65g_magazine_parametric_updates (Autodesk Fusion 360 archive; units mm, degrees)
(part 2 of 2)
fillet "Fillet14" radius 1
sweep "Sweep2" sketch "follower top profile" TwistAngle 0 TaperAngle 0
extrude "Extrude1" new body sketch "follower top profile" profile of L8 A5 A4 L7 L6 L4 A3 L2 A2 L3 A1 A6 L5 L1 A7 A8 L9 L12 A9 L13 A10 L17 L18 L20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 against normal blind 4 bodies "definesSketchPlane"
sketch "bullet offsetter bump" plane through (0, 0, -0.75) normal (0, 0, 1) x axis (1, 0, 0)
  line L1 (-7.25, 0) -> (7.25, 0)
  line L2 (-7.25, -4) -> (-7.25, 0)
  line L3 (7.25, -4) -> (-7.25, -4)
  line L4 (7.25, 0) -> (7.25, -4)
  line L5 (-10.25, 0) -> (-7.25, 0)
  line L6 (-10.25, -4) -> (-10.25, 0)
  line L7 (-7.25, -4) -> (-10.25, -4)
  line L8 (-7.25, 0) -> (-7.25, -4)
  line L9 (0.1, 0) -> (-10.25, 0)
  line L10 (0.1, 4.5) -> (0.1, 0)
  line L11 (-6.75, 4.5) -> (0.1, 4.5)
  line L12 (-10.25, 0) -> (-10.25, 1)
  line L13 (-10.25, 1) -> (-6.75, 4.5)
  point P7 (-10.25, 0)
  point P10 (-10.25, 0)
  point P13 (-10.25, 0)
  point P12 (-10.25, 4.5)
  point P14 (0.1, 4.5)
  point P15 (0.1, 4.5)
  point P11 (0.1, 0)
  point P16 (-6.75, 4.5)
  point P17 (-10.25, 1)
  coincident P7 P10
  perpendicular L6 L9
  perpendicular L1 L10
  coincident P7 P13
  horizontal L11
  vertical L12
  coincident P12 L11
  coincident P12 L12
  coincident P14 P15
  dimension "d900" distance P10 P11 = 10.35
  dimension "d903" distance P12 P16 = 3.5
  dimension "d904" distance P12 P17 = 3.5 (= "d903")
  dimension "d915" distance P11 P14 = 4.5
extrude "Extrude2" new body sketch "bullet offsetter bump" profile of L1 L5 L9 L10 L11 L12 L13 against normal blind 35.5
fillet "Fillet1" radius 3 2
fillet "Fillet6" radius 4
chamfer "Chamfer2" distance 4 distance 4
fillet "Fillet7" radius 2
fillet "Fillet8" radius 1
extrude "Extrude4" new body sketch "follower top profile" profile of L12 L13 A10 L18 L20 L19 A11 L52 blind -7 from offset -2
sweep "Sweep1" sketch "follower top profile" TwistAngle 0 TaperAngle 0
sweep "Sweep3" sketch "follower top profile" TwistAngle 0 TaperAngle 0
chamfer "Chamfer9" distance 0.7 distance 27
extrude "Extrude8" add sketch "follower top profile" profile of L15 L35 L36 L37 L38 L40 L41 L42 L43 against normal blind 5.5
extrude "Extrude9" add sketch "follower top profile" profile of L9 L35 L36 L37 L38 L40 L41 L42 L43 blind -2 from offset -5.5
fillet "Fillet9" radius 1.5
fillet "Fillet10" radius 1.5
combine "Combine2"
chamfer "Chamfer7" distance 0.5 distance 1
fillet "Fillet11" radius 1
chamfer "Chamfer8" distance 0.5 distance 12
fillet "Fillet12" radius 2
move "Move2"
extrude "Extrude6" add sketch "matchingFloorPlate" profile of L2 L5 L11 L16 L23 L24 L25 L26 A15 A16 A17 A18 along normal blind 7
fillet "Fillet1" radius 0.5
sketch "springRetentionNew" plane through (0, 0, 0) normal (0, 1, 0) x axis (1, 0, 0)
  line L1 (4.25, 36.0809) -> (4.25, 12.5809)
  line L2 (6.25, 36.0809) -> (6.25, 12.5809)
  line L3 (-4.25, 12.5809) -> (-4.25, 36.0809)
  line L4 (-6.25, 12.5809) -> (-6.25, 36.0809)
  line L5 (7.75, 14.9309) -> (6.25, 14.9309)
  line L6 (7.75, 21.9309) -> (7.75, 14.9309)
  line L7 (6.25, 21.9309) -> (7.75, 21.9309)
  line L8 (6.25, 14.9309) -> (6.25, 21.9309)
  line L9 (0, 36.0809) -> (0, 12.5809)
  line L10 (0, 4.25) -> (0, 41.25)
  line L11 (-6.25, 14.9309) -> (-6.25, 21.9309)
  line L12 (-7.75, 14.9309) -> (-6.25, 14.9309)
  line L13 (-6.25, 21.9309) -> (-7.75, 21.9309)
  line L14 (-7.75, 21.9309) -> (-7.75, 14.9309)
  line L15 (2.2447, 6.3309) -> (-1.7458, 6.3309)
  line L16 (8.75, 13.9309) -> (5.25, 13.9309)
  line L17 (8.75, 22.9309) -> (8.75, 13.9309)
  line L18 (5.25, 22.9309) -> (8.75, 22.9309)
  line L19 (5.25, 13.9309) -> (5.25, 22.9309)
  line L20 (-5.25, 22.9309) -> (-8.75, 22.9309)
  line L21 (-5.25, 13.9309) -> (-5.25, 22.9309)
  line L22 (-8.75, 13.9309) -> (-5.25, 13.9309)
  line L23 (-8.75, 22.9309) -> (-8.75, 13.9309)
  arc A1 centre (0, 12.5809) radius 6.25 clockwise from (6.25, 12.5809) to (-6.25, 12.5809)
  arc A2 centre (0, 36.0809) radius 6.25 clockwise from (-6.25, 36.0809) to (6.25, 36.0809)
  arc A3 centre (0, 36.0809) radius 4.25 clockwise from (-4.25, 36.0809) to (4.25, 36.0809)
  arc A4 centre (0, 12.5809) radius 4.25 clockwise from (4.25, 12.5809) to (-4.25, 12.5809)
  point P18 (6.25, 14.9309)
  point P4 (0, 12.5809)
  point P22 (0, 12.5809)
  point P10 (0, 36.0809)
  point P23 (0, 36.0809)
  point P27 (-6.25, 14.9309)
  point P19 (7.75, 14.9309)
  point P28 (-7.75, 14.9309)
  point P20 (7.75, 21.9309)
  point P29 (-7.75, 21.9309)
  point P21 (6.25, 21.9309)
  point P26 (-6.25, 21.9309)
  horizontal L5
  vertical L6
  horizontal L7
  vertical L8
  coincident L2 P18
  coincident P4 P22
  coincident P10 P23
  symmetric P18 L10 P27
  symmetric P19 L10 P28
  symmetric P20 L10 P29
  symmetric P21 L10 P26
  perpendicular L10 L15
  tangent A1 L15
  dimension "d1054" distance P18 P19 = 1.5
  dimension "d1055" distance P18 P21 = 7
  dimension "d1056" distance L5 L15 = 8.6
  dimension "d1065" = 1
  dimension "d1066" = -1
extrude "Extrude7" add sketch "springRetentionNew" profile of A1 A2 A3 L1 L2 A4 L3 L4 L8 L11 L19 L18 L16 L22 L21 L20 against normal blind 4
extrude "Extrude8" add sketch "springRetentionNew" profile of L2 L4 L5 L6 L7 L8 L11 L12 L13 L14 to an object from offset -1.8034
draft "Draft1" Angle1 55 Angle2 0
draft "Draft2" Angle1 55 Angle2 0
chamfer "Chamfer1" distance 0.5
extrude "Extrude9" cut sketch "springRetentionNew" profile of L2 L4 L5 L6 L7 L8 L11 L12 L13 L14 L18 L17 L16 L22 L23 L20 along normal blind 4
fillet "Fillet2" radius 1
sketch "addtlReinforcement" plane through (0, -4, 0) normal (0, -1, 0) x axis (1, 0, 0)
  line L1 (7.75, -15.2462) -> (7.75, -21.6156)
  line L2 (6.43, -13.0458) -> (7.5692, -14.6727)
  line L3 (-7.5692, -14.6727) -> (-6.43, -13.0458)
  line L4 (-7.75, -21.6156) -> (-7.75, -15.2462)
  line L5 (-6.4308, -23.8149) -> (-7.5692, -22.1892)
  line L6 (-6.25, -36.0809) -> (-6.25, -24.3885)
  line L7 (6.25, -24.3885) -> (6.25, -36.0809)
  line L8 (7.5692, -22.1892) -> (6.4308, -23.8149)
  line L9 (-6.2963, -24.0877) -> (6.2963, -24.0877)
  line L10 (6.2977, -12.7801) -> (-6.2977, -12.7801)
  line L11 (7.75, -17.0877) -> (-7.75, -17.0877)
  line L12 (-7.75, -20.0877) -> (7.75, -20.0877)
  arc A1 centre (6.75, -21.6156) radius 1 clockwise from (7.75, -21.6156) to (7.5692, -22.1892)
  arc A2 centre (6.75, -15.2462) radius 1 clockwise from (7.5692, -14.6727) to (7.75, -15.2462)
  arc A3 centre (7.2492, -12.4723) radius 1 clockwise from (6.43, -13.0458) to (6.2493, -12.4872)
  arc A4 centre (0, -12.5809) radius 6.25 clockwise from (-6.2493, -12.4872) to (6.2493, -12.4872)
  arc A5 centre (-7.2492, -12.4723) radius 1 clockwise from (-6.2493, -12.4872) to (-6.43, -13.0458)
  arc A6 centre (-6.75, -15.2462) radius 1 clockwise from (-7.75, -15.2462) to (-7.5692, -14.6727)
  arc A7 centre (-6.75, -21.6156) radius 1 clockwise from (-7.5692, -22.1892) to (-7.75, -21.6156)
  arc A8 centre (-7.25, -24.3885) radius 1 clockwise from (-6.4308, -23.8149) to (-6.25, -24.3885)
  arc A9 centre (0, -36.0809) radius 6.25 clockwise from (6.25, -36.0809) to (-6.25, -36.0809)
  arc A10 centre (7.25, -24.3885) radius 1 clockwise from (6.25, -24.3885) to (6.4308, -23.8149)
  point P30 (6.2963, -24.0877)
  point P31 (-6.2963, -24.0877)
  point P32 (-6.2977, -12.7801)
  point P33 (6.2977, -12.7801)
  point P34 (-7.75, -17.0877)
  point P35 (7.75, -17.0877)
  point P36 (7.75, -20.0877)
  point P37 (-7.75, -20.0877)
  midpoint A10 P30
  midpoint A8 P31
  midpoint A5 P32
  midpoint A3 P33
  coincident L4 P34
  coincident L1 P35
  perpendicular L1 L11
  coincident L1 P36
  coincident L4 P37
  perpendicular L4 L12
  dimension "d1071" distance L11 L12 = 3
  dimension "d1072" distance L9 L12 = 4
extrude "Extrude10" add sketch "addtlReinforcement" profile of L1 L4 L11 L12 along normal blind 1 taper -30
fillet "Fillet3" radius 2 1
fillet "Fillet4" radius 0.25
fillet "Fillet5" radius 0.5
sketch "Sketch1" plane through (0, 0, 0) normal (1, 0, 0) x axis (0, 1, 0)
  line L1 (5.675, 0) -> (0, 0)
  line L2 (5.9411, 0.38) -> (5.675, 0)
  line L3 (5.9411, 1.45) -> (5.9411, 0.38)
  line L4 (4.775, 1.45) -> (5.9411, 1.45)
  line L5 (4.775, 2.64) -> (4.775, 1.45)
  line L6 (5.626, 3.1808) -> (4.775, 2.64)
  line L7 (5.0285, 30.441) -> (5.626, 3.1808)
  line L8 (4.305, 32.735) -> (5.0285, 30.441)
  line L9 (4.28, 38.81) -> (4.305, 32.735)
  line L10 (0, 38.7924) -> (4.28, 38.81)
  line L11 (0, 0) -> (0, 38.7924)
  line L12 (3.95, 38.7924) -> (0, 38.7924)
  line L13 (0, 55.88) -> (0, 38.7924)
  line L14 (0, 0) -> (0, 55.88)
  curve K1 (0, 55.88) -> (3.95, 38.7924)
  curve K2 (-0.929, 55.88) -> (0.929, 55.88)
  curve K3 (3.95, 40.5596) -> (3.95, 37.0251)
  point P1 (0, 0)
  point P2 (0, 0)
  point P15 (0, 0)
  point P14 (0, 55.88)
  point P13 (3.95, 38.7924)
  point P3 (5.675, 0)
  point P6 (4.775, 1.45)
  point P7 (4.775, 2.64)
  point P4 (5.9411, 0.38)
  point P5 (5.9411, 1.45)
  point P8 (5.626, 3.1808)
  point P9 (5.0285, 30.441)
  point P10 (4.305, 32.735)
  point P11 (4.28, 38.81)
  point P12 (0, 38.7924)
  coincident P1 P2
  horizontal L1
  perpendicular L1 L3
  perpendicular L3 L4
  perpendicular L4 L5
  perpendicular L9 L10
  vertical L11
  perpendicular L11 L12
  perpendicular L12 L13
  coincident P1 P15
  midpoint P14 K2
  horizontal K2
  midpoint P13 K3
  vertical K3
  dimension "d1114" distance P2 P3 = 5.675 (= "( 11.35 / 2 ) * 1 mm")
  dimension "d1115" distance L5 L11 = 4.775 (= "( 9.55 / 2 ) * 1 mm")
  dimension "d1116" distance P6 P7 = 1.19
  dimension "d1117" distance L1 L4 = 1.45
  dimension "d1120" angle L1 L2 = 125 (= "90 deg + 35 deg")
  dimension "d1121" distance P4 P5 = 1.07
  dimension "d1122" distance P8 L11 = 5.626 (= "( 11.252 / 2 ) * 1 mm")
  dimension "d1123" distance P9 L11 = 5.0285 (= "( 10.057 / 2 ) * 1 mm")
  dimension "d1124" distance L1 P9 = 30.441
  dimension "d1125" distance L1 P10 = 32.735
  dimension "d1126" distance P10 L11 = 4.305 (= "( 8.61 / 2 ) * 1 mm")
  dimension "d1127" distance P11 L11 = 4.28 (= "( 8.56 / 2 ) * 1 mm")
  dimension "d1129" distance L1 P11 = 38.81
  dimension "d1130" distance P12 P13 = 3.95
  dimension "d1131" distance P1 P14 = 55.88
  dimension "d1136" angle L7 L11 = 1.256
revolve "Revolve1" sketch "Sketch1" AlongAngle 360
sketch "Sketch2" plane through (0, 0, 0) normal (0, 0, -1) x axis (-1, 0, 0)
  line L1 (84.8237, -5.675) -> (-1.9926, -5.675)
  line L2 (-1.9926, 16.325) -> (-1.9926, -5.675)
  line L3 (84.8237, 16.325) -> (-1.9926, 16.325)
  line L4 (84.8237, 16.325) -> (84.8237, -5.675)
  circle C1 centre (0, 0) radius 5.675
  circle C2 centre (0, 0) radius 2.1971
  point P1 (0, 0)
  point P3 (0, 0)
  point P4 (-1.9926, -5.675)
  point P6 (-1.9926, 16.325)
  coincident P1 P3
  horizontal L1
  tangent C1 L1
  perpendicular L1 L2
  perpendicular L2 L3
  dimension "d1133" diameter C2 = 4.3942
  dimension "d1138" distance P4 P6 = 22
extrude "Extrude1" cut sketch "Sketch2" profile of C2 against normal blind 3.1242
copy_paste_bodies "CopyPasteBodies2"
move "Move2"
copy_paste_bodies "CopyPasteBodies3"
move "Move3"
move "Move4"
copy_paste_bodies "CopyPasteBodies4"
move "Move5"
copy_paste_bodies "CopyPasteBodies5"
move "Move6"
copy_paste_bodies "CopyPasteBodies6"
move "Move7"
copy_paste_bodies "CopyPasteBodies7"
move "Move8"
copy_paste_bodies "CopyPasteBodies8"
move "Move9"
copy_paste_bodies "CopyPasteBodies9"
move "Move10"
copy_paste_bodies "CopyPasteBodies10"
move "Move11"
move "Move12"
move "Move13"
move "Move14"
move "Move15"
move "Move16"
move "Move17"
move "Move18"
move "Move19"
extrude "Extrude1" new body sketch "Sketch2" against normal blind 60
draft "Draft1" Angle1 -1.25 Angle2 0
shell "Shell1" outerThickness 2
sketch "Sketch1" plane through (0, 18.3168, 0.3997) normal (0, 0.9998, 0.0218) x axis (1, 0, 0)
  line L1 (-86.8237, 2.4002) -> (3.9926, 2.4002)
  line L2 (-86.8237, -61.615) -> (-86.8237, 2.4002)
  line L3 (3.9926, -61.615) -> (-86.8237, -61.615)
  line L4 (3.9926, 2.4002) -> (3.9926, -61.615)
  line L5 (-5.0074, -52.615) -> (-77.8237, -52.615)
  line L6 (-5.0074, -6.5998) -> (-5.0074, -52.615)
  line L7 (-77.8237, -6.5998) -> (-5.0074, -6.5998)
  line L8 (-77.8237, -52.615) -> (-77.8237, -6.5998)
  curve K1 (-46.7288, -36.635) -> (-43.8154, -53.9119)
  curve K2 (-43.8154, -53.9119) -> (-54.0221, -39.671)
  line L9 (-48.7358, -30.8899) -> (-46.4242, -36.508)
  line L10 (-56.6846, -34.1988) -> (-54.3268, -39.7977)
  line L11 (-48.9495, -28.494) -> (-48.7358, -30.8899)
  line L12 (-58.2341, -32.359) -> (-56.6846, -34.1988)
  line L13 (-58.8742, -3.0977) -> (-48.9495, -28.494)
  line L14 (-69.2621, -7.4219) -> (-58.2341, -32.359)
  line L15 (-69.2621, -7.4219) -> (-68.6843, -6.5956)
  line L16 (-58.8742, -3.0977) -> (-59.8677, -2.9255)
  line L17 (-60.3249, -1.8271) -> (-59.8677, -2.9255)
  line L18 (-69.1415, -5.4973) -> (-68.6843, -6.5956)
  line L19 (-59.6597, -0.3909) -> (-59.2485, -1.3787)
  line L20 (-70.6293, -4.9573) -> (-70.2181, -5.9451)
  line L21 (-70.6293, -4.9573) -> (-70.5297, -4.5042)
  line L22 (-59.6597, -0.3909) -> (-60.0513, -0.1423)
  closed curve K3 centre (-53.5918, -30.4265)
  closed curve K4 centre (-64.0681, -5.2598)
  closed curve K5 centre (-50.3755, -38.1528)
  closed curve K6 centre (-64.7333, -3.6619)
  closed curve K7 centre (-64.7333, -3.6619)
  closed curve K8 centre (-65.2905, -2.3233)
  dimension "d1148" = -9
  dimension "d1153" angle L8 L14 = 23.856
extrude "Extrude2" cut sketch "Sketch1" profile of L7 L8 L6 L5 against normal blind 65
extrude "Extrude3" cut of existing geometry blind -10
sketch "Sketch3" plane through (0, 0, -2) normal (0, 0, -1) x axis (-1, 0, 0)
  line L1 (86.8237, -7.7191) -> (-3.9926, -7.7191)
  line L2 (86.8237, 18.3691) -> (86.8237, -7.7191)
  line L3 (-3.9926, 18.3691) -> (86.8237, 18.3691)
  line L4 (-3.9926, -7.7191) -> (-3.9926, 18.3691)
  line L5 (84.8237, 16.325) -> (84.8237, -5.675)
  line L6 (84.8237, -5.675) -> (-1.9926, -5.675)
  line L7 (84.8237, 16.325) -> (-1.9926, 16.325)
  line L8 (79.3394, 16.325) -> (79.3394, -5.675)
  line L9 (68.6888, -5.675) -> (79.3394, -5.675)
  line L10 (74.8883, 8.8792) -> (68.6888, 1.5284)
  line L11 (74.8883, 16.325) -> (74.8883, 8.8792)
  line L12 (68.6888, 1.5284) -> (68.6888, -5.675)
  point P10 (79.3394, -5.675)
  point P11 (79.3394, 16.325)
  point P12 (68.6888, -5.675)
  point P15 (74.8883, 16.325)
  coincident L6 P10
  coincident L7 P11
  perpendicular L7 L8
  coincident L6 P12
  coincident L7 P15
  perpendicular L7 L11
  perpendicular L6 L12
extrude "Extrude3" new body sketch "Sketch3" profile of L6 L7 L8 L9 L10 L11 L12 blind -53 from offset -4
move "Move20"
remove_body "RemoveBody2"
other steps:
base_feature "Base Feature2"
base_feature "Base Feature3"
base_feature "Base Feature4"
base_feature "Base Feature5"
base_feature "Base Feature6"
base_feature "Base Feature7"
base_feature "Base Feature8"
base_feature "Base Feature9"
base_feature "Base Feature10"
derived_base_feature "Derived Base Feature1" bodies "floor plate"
extrude "Extrude4" cut sketch "cut draft angle between feed lips" profile of L1 L2 L3 L4 L5 against normal blind 13.5
extrude "Extrude11" cut sketch "Rear locking lug profile" profile of L3 A1 L6 L7 L8 distance 5.8
create_component "CreateComponent2"
create_component "CreateComponent3"
create_component "CreateComponent4"
create_component "CreateComponent5"
create_component "CreateComponent6"
named bodies: "follower", "mag body", "feed geometry", "random cube", "placeholder to establish center", "SUPPORT V1", "feed geometry (1)", "main body", "draft tool", "feed lip", "feed lip (1)", "floor plate", "floorPlate", "true rear lock lug", "MagpulFollower_223556", "MagpulFollower_223556 (1)", "MagpulFollower_223556 (2)", "MagpulFollower_223556 (3)", "MagpulFollower_223556 (4)", "definesSketchPlane", "Follower", "updated lock lug", "template lock lug from m76", "updated locking lug"

design "65_g_floorplate"
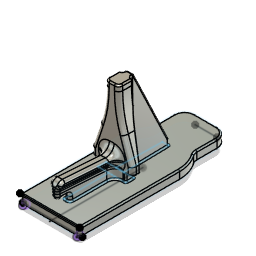
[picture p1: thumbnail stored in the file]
sketch "top profile" plane through (0, 0, 0) normal (0, 1, 0) x axis (1, 0, 0)
  line L1 (20.7, 0) -> (0, 0)
  line L2 (20.7, 38.9995) -> (20.7, 0)
  line L3 (18.085, 52.7) -> (18.085, 38.9995)
  line L4 (5.315, 55.4) -> (15.385, 55.4)
  line L5 (2.615, 39.6) -> (2.615, 52.7)
  line L6 (0, 39.6) -> (2.615, 39.6)
  line L7 (0, 0) -> (0, 39.6)
  line L8 (2.615, 39.6) -> (0, 39.6)
  line L9 (20.7, 38.9995) -> (18.085, 38.9995)
  curve K1 (20.7, 38.9995) -> (18.085, 44.77)
  curve K2 (19.0439, 42.5779) -> (18.3507, 43.501)
  line L10 (10.35, 55.4) -> (10.35, 0)
  curve K3 (0, 38.9995) -> (2.615, 44.77)
  curve K4 (18.1695, 43.9977) -> (18.0005, 45.5423)
  curve K5 (20.6925, 38.3395) -> (20.7075, 39.6594)
  curve K6 (2.5305, 43.9977) -> (2.6995, 45.5423)
  curve K7 (1.6561, 42.5779) -> (2.3493, 43.501)
  curve K8 (0.0075, 38.3395) -> (-0.0075, 39.6594)
  line L11 (0, 38.9995) -> (2.615, 38.9995)
  line L12 (2.615, 55.4) -> (2.615, 38.9995)
  line L13 (10.35, 0) -> (0, 0)
  line L14 (10.35, 36.4) -> (10.35, 0)
  line L15 (0, 36.4) -> (10.35, 36.4)
  line L16 (0, 0) -> (0, 36.4)
  line L17 (5.175, 28.09) -> (5.175, 36.4)
  line L18 (0, 29.925) -> (0, 36.4)
  line L19 (4.421, 36.4) -> (0, 36.4)
  line L20 (5.563, 36.4) -> (4.421, 36.4)
  line L21 (0, 992.6) -> (0, 0)
  line L22 (66.3724, 992.6) -> (0, 992.6)
  arc A1 centre (5.315, 52.7) radius 2.7 clockwise from (2.615, 52.7) to (5.315, 55.4)
  arc A2 centre (15.385, 52.7) radius 2.7 clockwise from (15.385, 55.4) to (18.085, 52.7)
  point P1 (0, 0)
  point P2 (0, 0)
  point P10 (18.085, 44.77)
  point P11 (18.6973, 43.0394)
  point P4 (20.7, 38.9995)
  point P20 (0, 38.9995)
  point P6 (18.085, 38.9995)
  point P31 (2.615, 38.9995)
  point P7 (18.085, 55.4)
  point P32 (2.615, 55.4)
  point P17 (2.615, 44.77)
  point P18 (2.0027, 43.0394)
  point P12 (20.041, 41.5358)
  point P19 (0.659, 41.5358)
  point P13 (18.3507, 43.501)
  point P27 (2.3493, 43.501)
  point P14 (19.0439, 42.5779)
  point P28 (1.6561, 42.5779)
  point P21 (18.0005, 45.5423)
  point P25 (2.6995, 45.5423)
  point P22 (18.1695, 43.9977)
  point P26 (2.5305, 43.9977)
  point P23 (20.7075, 39.6594)
  point P29 (-0.0075, 39.6594)
  point P24 (20.6925, 38.3395)
  point P30 (0.0075, 38.3395)
  point P16 (10.35, 55.4)
  point P8 (2.615, 55.4)
  point P15 (10.35, 0)
  point P3 (20.7, 0)
  point P43 (0, 0)
  point P46 (0, 36.4)
  point P47 (5.175, 36.4)
  point P41 (0, 0)
  point P42 (0, 0)
  point P40 (20.7, 0)
  point P52 (0, 0)
  point P44 (10.35, 0)
  point P45 (10.35, 36.4)
  point P48 (5.175, 28.09)
  point P49 (0, 29.925)
  point P50 (4.421, 36.4)
  point P51 (5.563, 36.4)
  point P53 (0, 992.6)
  coincident P1 P2
  horizontal L1
  perpendicular L1 L2
  perpendicular L3 L4
  perpendicular L1 L7
  perpendicular L5 L8
  perpendicular L2 L9
  coincident L3 P10
  midpoint P11 K2
  midpoint P10 K4
  midpoint P4 K5
  symmetric P4 L10 P20
  symmetric P6 L10 P31
  symmetric P7 L10 P32
  symmetric P10 L10 P17
  symmetric P11 L10 P18
  symmetric P12 L10 P19
  symmetric P13 L10 P27
  symmetric P14 L10 P28
  symmetric L10 P21 P25
  symmetric L10 P22 P26
  symmetric L10 P23 P29
  symmetric L10 P24 P30
  coincident L4 P16
  coincident P8 L4
  coincident P8 L5
  tangent L4 A1
  tangent L5 A1
  coincident P7 L3
  coincident P7 L4
  tangent L3 A2
  tangent L4 A2
  coincident L1 P15
  coincident P3 L1
  coincident P3 L2
  coincident P2 L1
  coincident P1 P43
  perpendicular L10 L13
  perpendicular L1 L14
  coincident L7 P46
  perpendicular L7 L15
  midpoint L15 P47
  perpendicular L15 L17
  perpendicular L15 L18
  perpendicular L7 L19
  perpendicular L17 L20
  coincident P1 P41
  parallel L1 L13
  coincident P2 P42
  coincident P3 P40
  coincident P2 P52
  perpendicular L13 L21
  perpendicular L21 L22
  dimension "d1" distance P2 P3 = 20.7
  dimension "d5" distance P7 P8 = 15.47
  dimension "d7" radius A1 = 2.7
  dimension "d8" radius A2 = 2.7
  dimension "d11" distance P43 P44 = 10.35
  dimension "d12" distance P44 P45 = 36.4
  dimension "d13" distance P47 P48 = 8.31
  dimension "d14" distance P46 P49 = 6.475
  dimension "d15" distance P46 P50 = 4.421
  dimension "d16" distance P50 P51 = 1.142
  dimension "d55" distance P52 P53 = 992.6
  dimension "d263" diameter = 11.2
  dimension "d264" diameter = 11.2
  dimension "d265" diameter = 11.2
  dimension "d266" distance = 5.6
  dimension "d267" distance = 9.5
  dimension "d268" distance = 4.5
  dimension "d269" distance = 5.6
  dimension "d270" distance = 0.5495
  dimension "d271" diameter = 11.2
  dimension "d272" diameter = 11.2
  dimension "d273" diameter = 11.2
  dimension "d274" diameter = 11.2
  dimension "d275" diameter = 11.2
  dimension "d276" distance = 22
  dimension "d277" diameter = 11.2
  dimension "d278" distance = 22
  dimension "d279" diameter = 11.2
  dimension "d280" diameter = 11.2
  dimension "d281" diameter = 11.2
  dimension "d282" distance = 9.5
  dimension "d283" distance = 4.5
  dimension "d284" diameter = 11.2
  dimension "d285" distance = 4.5
  dimension "d286" distance = 9.5
  dimension "d287" distance = 54.4
  dimension "d296" distance = 47
  dimension "d298" distance = 7
  dimension "d299" distance = 5
  dimension "d300" distance = 20
  dimension "d301" distance = 32
  dimension "d302" distance = 36
extrude "Extrude1" new body sketch "top profile" profile of L1 L7 L10 L13 L14 L15 L16 L18 L20 along normal blind 4.5
fillet "Fillet1" radius 3
sketch "uppermost feature" plane through (0, 4.5, 0) normal (0, 1, 0) x axis (-1, 0, 0)
  line L1 (0, -36.4) -> (-10.35, -36.4)
  line L2 (0, 0) -> (0, -36.4)
  line L3 (-10.35, 0) -> (0, 0)
  line L4 (-10.35, -36.4) -> (-10.35, 0)
split "Split1"
combine "Combine1"
chamfer "Chamfer2" distance 4 Rotate Angle 30
chamfer "Chamfer4" distance 3 Rotate Angle 60
draft "Draft2" Angle1 40 Angle2 0
chamfer "Chamfer5" distance 3 Rotate Angle 50
fillet "Fillet4" radius 3
fillet "Fillet5" radius 1.25
fillet "Fillet6" radius 9.5
fillet "Fillet7" radius 2
fillet "Fillet8" radius 1.5
fillet "Fillet9" radius 10.5
fillet "Fillet10" radius 1.5
revolve "Revolve1" sketch "top profile" AlongAngle -0.183
offset_faces "OffsetFaces1" distance 4
offset_faces "OffsetFaces2" distance 4
fillet "Fillet11" radius 11
fillet "Fillet12" radius 4.5
fillet "Fillet13" radius 2
fillet "Fillet14" radius 2
fillet "Fillet15" radius 0.75
sketch "bottom spring support" plane through (0, -3.1703, -0.0101) normal (0, -1, -0.0032) x axis (-1, 0, 0)
  line L1 (0, 35.8746) -> (0, 1.9949)
  line L2 (-2.615, 52.6949) -> (-2.615, 44.4901)
  line L3 (-15.385, 55.3949) -> (-5.315, 55.3949)
  line L4 (-18.085, 44.4901) -> (-18.085, 52.6949)
  line L5 (-20.7, 1.9949) -> (-20.7, 35.8746)
  line L6 (-2, -0.0051) -> (-18.7, -0.0051)
  line L7 (-20.7, 35.4949) -> (-20.7, -0.0051)
  line L8 (-19.062, 35.4949) -> (-20.7, 35.4949)
  line L9 (-24.0146, 1.1159) -> (-24.0146, -0.0051)
  line L10 (-19.062, 1.1159) -> (-19.062, 35.4949)
  line L11 (-10.35, 36.3998) -> (-10.35, 0)
  line L12 (-1.638, 35.4949) -> (0, 35.4949)
  line L13 (0, 0) -> (0, 35.4949)
  line L14 (-20.7, -0.0051) -> (0, 0)
  line L15 (-1.638, 1.1159) -> (-1.638, 35.4949)
  line L16 (-19.062, 1.1159) -> (-1.638, 1.1159)
  arc A1 centre (-2, 1.9949) radius 2 clockwise from (0, 1.9949) to (-2, -0.0051)
  arc A2 centre (-11, 35.8746) radius 11 clockwise from (-1.8558, 41.9888) to (0, 35.8746)
  arc A3 centre (-5.315, 52.6949) radius 2.7 clockwise from (-5.315, 55.3949) to (-2.615, 52.6949)
  arc A4 centre (-15.385, 52.6949) radius 2.7 clockwise from (-18.085, 52.6949) to (-15.385, 55.3949)
  arc A5 centre (-9.7, 35.8746) radius 11 clockwise from (-20.7, 35.8746) to (-18.8442, 41.9888)
  arc A6 centre (-18.7, 1.9949) radius 2 clockwise from (-18.7, -0.0051) to (-20.7, 1.9949)
  arc A7 centre (1.885, 44.4901) radius 4.5 clockwise from (-1.8558, 41.9888) to (-2.615, 44.4901)
  arc A8 centre (-22.585, 44.4901) radius 4.5 clockwise from (-18.085, 44.4901) to (-18.8442, 41.9888)
  point P23 (-20.7, 35.4949)
  point P30 (0, 35.4949)
  point P24 (-19.062, 35.4949)
  point P31 (-1.638, 35.4949)
  point P1 (0, 0)
  point P32 (0, 0)
  point P33 (0, 0)
  point P25 (-24.0146, -0.0051)
  point P26 (-24.0146, 1.1159)
  perpendicular L6 L7
  perpendicular L7 L8
  symmetric P23 L11 P30
  symmetric P24 L11 P31
  coincident P1 P32
  perpendicular L12 L13
  coincident P1 P33
  perpendicular L10 L16
  dimension "d70" distance P23 P24 = 1.638
  dimension "d71" distance P25 P26 = 1.121
revolve "Revolve2" sketch "bottom spring support" AlongAngle 2.7
fillet "Fillet18" radius 1.75
fillet "Fillet17" radius 0.75
sketch "cartrige ref dims" plane through (0, 0, 0) normal (0, 1, 0) x axis (1, 0, 0)
  line L1 (32, 0) -> (0, 0)
  line L2 (32, 32.242) -> (32, 0)
  line L3 (40.4093, 0) -> (32, 0)
  line L4 (40.4093, 29.227) -> (40.4093, 0)
  line L5 (51, 0) -> (40.4093, 0)
  line L6 (51, 54.32) -> (51, 0)
  line L7 (55.5931, 0) -> (51, 0)
  line L8 (55.5931, 57.4) -> (55.5931, 0)
  point P1 (0, 0)
  point P2 (0, 0)
  point P3 (32, 0)
  point P4 (32, 32.242)
  point P5 (40.4093, 0)
  point P6 (40.4093, 29.227)
  point P7 (51, 0)
  point P8 (51, 54.32)
  point P9 (55.5931, 0)
  point P10 (55.5931, 57.4)
  coincident P1 P2
  horizontal L1
  perpendicular L1 L2
  perpendicular L2 L3
  perpendicular L3 L4
  perpendicular L4 L5
  perpendicular L5 L6
  perpendicular L6 L7
  perpendicular L7 L8
  dimension "d79" distance P3 P4 = 32.242
  dimension "d80" distance P5 P6 = 29.227
  dimension "d81" distance P7 P8 = 54.32
  dimension "d82" distance P9 P10 = 57.4
sketch "mag body proper" plane through (0, 0, 0) normal (0, 1, 0) x axis (1, 0, 0)
  line L1 (2.615, 52.7048) -> (2.615, 44.5)
  line L2 (15.385, 55.4048) -> (5.315, 55.4048)
  line L3 (18.085, 44.5) -> (18.085, 52.7048)
  curve K1 (0.0859, 37.2565) -> (0.0311, 36.7114)
  line L4 (0.0311, 36.7114) -> (0, 36.7114)
  curve K2 (20.6689, 36.7114) -> (20.6141, 37.2565)
  line L5 (20.7, 36.7114) -> (20.6689, 36.7114)
  line L6 (20.7, 3.2538) -> (20.7, 36.7114)
  line L7 (20.7, 2.0003) -> (20.7, 3.2538)
  curve K3 (8.3837, 0.0003) -> (8.35, 0)
  line L8 (15.385, 55.4048) -> (5.315, 55.4048)
  line L9 (10.35, 56.4025) -> (10.35, -0.9975)
  line L10 (-0.65, 35.6726) -> (-0.65, -0.9975)
  line L11 (-0.65, 43) -> (-0.65, 43)
  line L12 (2.35, 52.4025) -> (2.35, 45)
  line L13 (10.35, 56.4025) -> (6.35, 56.4025)
  line L14 (-0.65, -0.9975) -> (10.35, -0.9975)
  line L15 (21.35, -0.9975) -> (10.35, -0.9975)
  line L16 (21.35, 35.6726) -> (21.35, -0.9975)
  line L17 (18.35, 52.4025) -> (18.35, 45)
  line L18 (10.35, 56.4025) -> (14.35, 56.4025)
  line L19 (23.35, 35.6726) -> (23.35, -2.9975)
  line L20 (23.35, -2.9975) -> (17.85, -2.9975)
  line L21 (-2.65, -2.9975) -> (5.1769, -2.9975)
  line L22 (10.35, 60.8025) -> (10.35, 56.4025)
  line L23 (15.85, -4.9975) -> (10.35, -4.9975)
  line L24 (17.85, -2.9975) -> (15.85, -4.9975)
  line L25 (19.097, -4.9975) -> (15.85, -4.9975)
  line L26 (-2.65, -2.9975) -> (2.85, -2.9975)
  line L27 (2.85, -2.9975) -> (4.85, -4.9975)
  line L28 (4.85, -4.9975) -> (10.35, -4.9975)
  line L29 (17.85, -2.9975) -> (2.85, -2.9975)
  line L30 (-0.58, -0.9275) -> (10.35, -0.9275)
  line L31 (-0.58, 35.6726) -> (-0.58, -0.9275)
  line L32 (2.42, 52.4025) -> (2.42, 45)
  line L33 (10.35, 56.3325) -> (6.35, 56.3325)
  line L34 (10.35, 56.3325) -> (14.35, 56.3325)
  line L35 (18.28, 52.4025) -> (18.28, 45)
  line L36 (21.28, 35.6726) -> (21.28, -0.9275)
  line L37 (21.28, -0.9275) -> (10.35, -0.9275)
  closed curve K4 centre (11, 35.8845)
  closed curve K5 centre (-1.885, 44.5)
  closed curve K6 centre (5.315, 52.7048)
  closed curve K7 centre (15.385, 52.7048)
  closed curve K8 centre (22.585, 44.5)
  closed curve K9 centre (9.7, 35.8845)
  arc A1 centre (-0.65, 45) radius 3 clockwise from (2.35, 45) to (1.7875, 43.2511)
  arc A2 centre (12.35, 35.6726) radius 13 clockwise from (-0.65, 35.6726) to (1.7875, 43.2511)
  arc A3 centre (21.35, 45) radius 3 clockwise from (18.9125, 43.2511) to (18.35, 45)
  arc A4 centre (6.35, 52.4025) radius 4 clockwise from (2.35, 52.4025) to (6.35, 56.4025)
  arc A5 centre (8.35, 35.6726) radius 13 clockwise from (18.9125, 43.2511) to (21.35, 35.6726)
  arc A6 centre (21.35, 45) radius 3 clockwise from (18.9125, 43.2511) to (18.35, 45)
  arc A7 centre (14.35, 52.4025) radius 4 clockwise from (14.35, 56.4025) to (18.35, 52.4025)
  arc A8 centre (19.35, 54.3429) radius 2 clockwise from (20.7827, 55.7384) to (21.35, 54.3429)
  arc A9 centre (12.35, 35.6726) radius 12.93 clockwise from (-0.58, 35.6726) to (1.8444, 43.2103)
  arc A10 centre (-0.65, 45) radius 3.07 clockwise from (2.42, 45) to (1.8444, 43.2103)
  arc A11 centre (6.35, 52.4025) radius 3.93 clockwise from (2.42, 52.4025) to (6.35, 56.3325)
  arc A12 centre (14.35, 52.4025) radius 3.93 clockwise from (14.35, 56.3325) to (18.28, 52.4025)
  arc A13 centre (21.35, 45) radius 3.07 clockwise from (18.8556, 43.2103) to (18.28, 45)
  arc A14 centre (8.35, 35.6726) radius 12.93 clockwise from (18.8556, 43.2103) to (21.28, 35.6726)
  point P8 (5.315, 55.4048)
  point P26 (5.315, 55.4048)
  point P10 (15.385, 55.4048)
  point P27 (15.385, 55.4048)
  point P33 (2.35, 45)
  point P40 (18.35, 45)
  point P36 (1.7875, 43.2511)
  point P38 (18.9125, 43.2511)
  point P28 (10.35, -0.9975)
  point P44 (10.35, -0.9975)
  point P29 (10.35, 56.4025)
  point P53 (10.35, 56.4025)
  point P30 (-0.65, -0.9975)
  point P45 (21.35, -0.9975)
  point P50 (18.35, 45)
  point P35 (-0.65, 35.6726)
  point P46 (21.35, 35.6726)
  point P48 (18.9125, 43.2511)
  point P41 (2.35, 52.4025)
  point P51 (18.35, 52.4025)
  point P42 (6.35, 56.4025)
  point P52 (14.35, 56.4025)
  point P56 (23.35, -2.9975)
  point P71 (-2.65, -2.9975)
  point P66 (10.35, -4.9975)
  point P73 (10.35, -4.9975)
  point P67 (15.85, -4.9975)
  point P72 (4.85, -4.9975)
  point P69 (17.85, -2.9975)
  point P70 (2.85, -2.9975)
  point P5 (2.615, 44.5)
  coincident P8 P26
  coincident P10 P27
  perpendicular L2 L9
  horizontal L11
  tangent L11 A1
  tangent L12 A1
  tangent L10 A2
  tangent A1 A2
  perpendicular L9 L13
  perpendicular L10 L14
  symmetric L9 P33 P40
  symmetric L9 A1 A3
  symmetric L9 P36 P38
  tangent L12 A4
  tangent L13 A4
  symmetric P28 L9 P44
  symmetric P29 L9 P53
  symmetric L9 P30 P45
  symmetric L9 P33 P50
  symmetric L9 A1 A6
  symmetric L9 P35 P46
  symmetric L9 P36 P48
  symmetric L9 A2 A5
  symmetric L9 P41 P51
  symmetric L9 P42 P52
  symmetric L9 A4 A7
  perpendicular L18 L22
  perpendicular L9 L23
  horizontal L25
  symmetric L9 P56 P71
  symmetric L9 P66 P73
  symmetric L9 P67 P72
  symmetric L9 P69 P70
  parallel L20 L29
  dimension "d85" distance P28 P29 = 57.4
  dimension "d92" radius A1 = 3
  dimension "d94" radius A2 = 13
  dimension "d95" distance P28 P30 = 11
  dimension "d96" radius A4 = 4
  dimension "d97" distance P30 P35 = 36.6701
  dimension "d98" distance P30 P36 = 44.2486
  dimension "d99" distance P5 P30 = 45.4975
  dimension "d100" distance P30 P41 = 53.4
  dimension "d111" radius A8 = 2
  dimension "d113" distance P66 P67 = 5.5
  dimension "d114" angle L24 L25 = 45
  dimension "d303" = 0.07
work_plane "WorkPlane1" AlongDistance -60.803
work_plane "WorkPlane2" AlongDistance 8
extrude "Extrude15" cut blind -26
extrude "Extrude18" cut distance 6.19
extrude "Extrude19" new body sketch "mag body proper" profile of L9 L37 L36 A14 A11 L30 A13 L31 A10 L32 L34 A9 L35 A12 L33 along normal blind 3.43
sketch "extruded features z" plane through (0, 3.43, 0) normal (0, 1, 0) x axis (-1, 0, 0)
  line L1 (-21.28, 0.9275) -> (0.58, 0.9275)
  line L2 (-21.28, -35.6726) -> (-21.28, 0.9275)
  line L3 (-18.28, -52.4025) -> (-18.28, -45)
  line L4 (-6.35, -56.3325) -> (-14.35, -56.3325)
  line L5 (-2.42, -45) -> (-2.42, -52.4025)
  line L6 (0.58, 0.9275) -> (0.58, -35.6726)
  line L7 (0.58, 0.9275) -> (-21.28, 0.9275)
  line L8 (-15.45, -21.7725) -> (-10.35, -21.7725)
  line L9 (-5.25, -21.7725) -> (-10.35, -21.7725)
  line L10 (-5.25, -24.7725) -> (-5.25, -21.7725)
  line L11 (-15.45, -24.7725) -> (-5.25, -24.7725)
  line L12 (-15.45, -21.7725) -> (-15.45, -24.7725)
  line L13 (-11.475, -5.2725) -> (-10.35, -5.2725)
  line L14 (-9.225, -5.2725) -> (-10.35, -5.2725)
  line L15 (-11.475, -21.7725) -> (-11.475, -5.2725)
  line L16 (-9.225, -21.7725) -> (-9.225, -5.2725)
  line L17 (-11.475, -41.4725) -> (-11.85, -24.7725)
  line L18 (-11.85, -24.7725) -> (-8.85, -24.7725)
  line L19 (-9.2256, -41.422) -> (-11.475, -41.4725)
  line L20 (-8.85, -24.7725) -> (-9.2256, -41.422)
  arc A1 centre (-8.35, -35.6726) radius 12.93 clockwise from (-18.8556, -43.2103) to (-21.28, -35.6726)
  arc A2 centre (-21.35, -45) radius 3.07 clockwise from (-18.8556, -43.2103) to (-18.28, -45)
  arc A3 centre (-14.35, -52.4025) radius 3.93 clockwise from (-14.35, -56.3325) to (-18.28, -52.4025)
  arc A4 centre (-6.35, -52.4025) radius 3.93 clockwise from (-2.42, -52.4025) to (-6.35, -56.3325)
  arc A5 centre (0.65, -45) radius 3.07 clockwise from (-2.42, -45) to (-1.8444, -43.2103)
  arc A6 centre (-12.35, -35.6726) radius 12.93 clockwise from (0.58, -35.6726) to (-1.8444, -43.2103)
  point P3 (-21.28, 0.9275)
  point P20 (-21.28, 0.9275)
  point P2 (0.58, 0.9275)
  point P21 (0.58, 0.9275)
  point P30 (-11.475, -21.7725)
  point P31 (-9.225, -21.7725)
  point P22 (-10.35, -21.7725)
  point P23 (-15.45, -21.7725)
  point P24 (-5.25, -21.7725)
  point P25 (-5.25, -24.7725)
  point P26 (-15.45, -24.7725)
  point P27 (-10.35, -5.2725)
  point P29 (-9.225, -5.2725)
  point P28 (-11.475, -5.2725)
  point P33 (-11.85, -24.7725)
  point P34 (-8.85, -24.7725)
  point P32 (-11.475, -41.4725)
  point P35 (-9.2256, -41.422)
  coincident P3 P20
  coincident P2 P21
  perpendicular L9 L10
  perpendicular L10 L11
  coincident L8 P30
  perpendicular L8 L15
  coincident L9 P31
  perpendicular L9 L16
  parallel L11 L18
  perpendicular L17 L19
  dimension "d307" distance P22 P23 = 5.1
  dimension "d308" distance P22 P24 = 5.1
  dimension "d309" distance P24 P25 = 3
  dimension "d310" distance P25 P26 = 10.2
  dimension "d313" distance P27 P29 = 1.125
  dimension "d314" distance L8 L13 = 16.5
  dimension "d335" distance P28 P29 = 2.25
  dimension "d339" distance P33 P34 = 3
  dimension "d340" distance P32 P35 = 2.25
extrude "Extrude20" add sketch "extruded features z" profile of L8 L9 L10 L11 L12 along normal blind 2.6
sketch "Sketch25" plane through (0, 6.03, 0) normal (0, 1, 0) x axis (-1, 0, 0)
  line L1 (-15.45, -21.7725) -> (-5.25, -21.7725)
  line L2 (-15.45, -24.7725) -> (-15.45, -21.7725)
  line L3 (-5.25, -24.7725) -> (-15.45, -24.7725)
  line L4 (-5.25, -21.7725) -> (-5.25, -24.7725)
  line L5 (-15.45, -21.7725) -> (-5.25, -21.7725)
  line L6 (-2.85, -21.7725) -> (-17.85, -21.7725)
  line L7 (-2.85, -24.7725) -> (-2.85, -21.7725)
  line L8 (-17.85, -24.7725) -> (-2.85, -24.7725)
  line L9 (-17.85, -21.7725) -> (-17.85, -24.7725)
  point P2 (-5.25, -21.7725)
  point P6 (-5.25, -21.7725)
  point P3 (-15.45, -21.7725)
  point P7 (-15.45, -21.7725)
  point P8 (-17.85, -21.7725)
  point P9 (-2.85, -21.7725)
  point P11 (-17.85, -24.7725)
  coincident P2 P6
  coincident P3 P7
  horizontal L6
  vertical L7
  horizontal L8
  vertical L9
  dimension "d319" distance P8 P9 = 15
  dimension "d320" distance P8 P11 = 3
extrude "Extrude21" add sketch "Sketch25" along normal blind 3
sketch "Sketch26" plane through (0, 9.03, 0) normal (0, 1, 0) x axis (-1, 0, 0)
  line L1 (-2.85, -24.7725) -> (-17.85, -24.7725)
  line L2 (-2.85, -21.7725) -> (-2.85, -24.7725)
  line L3 (-17.85, -21.7725) -> (-2.85, -21.7725)
  line L4 (-17.85, -24.7725) -> (-17.85, -21.7725)
  line L5 (25.5759, -27.2354) -> (28.5759, -27.2354)
  line L6 (25.5759, -24.2354) -> (25.5759, -27.2354)
  line L7 (28.5759, -24.2354) -> (25.5759, -24.2354)
  line L8 (28.5759, -27.2354) -> (28.5759, -24.2354)
  point P6 (28.5759, -27.2354)
  point P7 (25.5759, -27.2354)
  point P9 (28.5759, -24.2354)
  horizontal L5
  vertical L6
  horizontal L7
  vertical L8
  dimension "d323" distance P6 P7 = 3
  dimension "d324" distance P6 P9 = 3
extrude "Extrude22" new body sketch "Sketch26" profile of L1 L2 L3 L4 along normal blind 15
draft "Draft8" Angle1 18.5 Angle2 0
draft "Draft9" Angle1 8.5 Angle2 0
extrude "Extrude23" add of existing geometry blind 8.54
fillet "Fillet31" radius 40
combine "Combine2"
extrude "Extrude26" add sketch "extruded features z" profile of L11 L17 L18 L19 L20 to an object
chamfer "Chamfer6" distance 27 distance 13
fillet "Fillet35" radius 0.5
fillet "Fillet32" radius 1
fillet "Fillet33" radius 0.5
fillet "Fillet36" radius 0.49
fillet "Fillet37" radius 1.5
fillet "Fillet38" radius 0.5
extrude "Extrude27" add sketch "extruded features z" profile of L8 L9 L13 L14 L15 L16 along normal blind 2.6
sketch "Sketch27" plane through (0, 6.03, 0) normal (0, 1, 0) x axis (-1, 0, 0)
  line L1 (-11.475, -5.2725) -> (-9.225, -5.2725)
  line L2 (-11.475, -21.7725) -> (-11.475, -5.2725)
  line L3 (-9.225, -21.7725) -> (-11.475, -21.7725)
  line L4 (-9.225, -5.2725) -> (-9.225, -21.7725)
  line L5 (-9.225, -21.7725) -> (-11.475, -21.7725)
  line L6 (-11.475, -0.7725) -> (-11.475, -21.7725)
  line L7 (-9.225, -0.7725) -> (-9.225, -21.7725)
  line L8 (-11.475, -0.7725) -> (-9.225, -0.7725)
  point P4 (-11.475, -21.7725)
  point P6 (-11.475, -21.7725)
  point P5 (-9.225, -21.7725)
  point P7 (-9.225, -21.7725)
  point P8 (-11.475, -0.7725)
  point P9 (-9.225, -0.7725)
  coincident P4 P6
  coincident P5 P7
  perpendicular L3 L6
  perpendicular L3 L7
  dimension "d365" distance P6 P8 = 21
  dimension "d366" distance P7 P9 = 21
extrude "Extrude28" add sketch "Sketch27" along normal blind 2
draft "Draft10" Angle1 -4 Angle2 0
draft "Draft11" Angle1 4 Angle2 0
extrude "Extrude29" add of existing geometry blind 2 taper 4
extrude "Extrude30" add of existing geometry blind 2
extrude "Extrude31" add of existing geometry blind 0.6
extrude "Extrude32" add of existing geometry blind 0.6
fillet "Fillet39" radius 1.5 2 1
fillet "Fillet40" radius 1
fillet "Fillet41" radius 1
fillet "Fillet42" radius 3
fillet "Fillet45" radius 1
fillet "Fillet43" radius 0.5
sketch "Sketch28" plane through (0, 0, 0) normal (0, -1, 0) x axis (1, 0, 0)
  line L1 (0.42, 0.9275) -> (20.28, 0.9275)
  line L2 (-0.58, -35.6726) -> (-0.58, -0.0725)
  line L3 (2.42, -52.4025) -> (2.42, -45)
  line L4 (14.35, -56.3325) -> (6.35, -56.3325)
  line L5 (18.28, -45) -> (18.28, -52.4025)
  line L6 (21.28, -0.0725) -> (21.28, -35.6726)
  line L7 (21.28, -0.0725) -> (-0.58, -0.0725)
  line L8 (6.35, -56.3325) -> (14.35, -56.3325)
  line L9 (10.35, -33.0725) -> (10.35, 0.9275)
  arc A1 centre (12.35, -35.6726) radius 12.93 clockwise from (1.8444, -43.2103) to (-0.58, -35.6726)
  arc A2 centre (-0.65, -45) radius 3.07 clockwise from (1.8444, -43.2103) to (2.42, -45)
  arc A3 centre (6.35, -52.4025) radius 3.93 clockwise from (6.35, -56.3325) to (2.42, -52.4025)
  arc A4 centre (14.35, -52.4025) radius 3.93 clockwise from (18.28, -52.4025) to (14.35, -56.3325)
  arc A5 centre (21.35, -45) radius 3.07 clockwise from (18.28, -45) to (18.8556, -43.2103)
  arc A6 centre (8.35, -35.6726) radius 12.93 clockwise from (21.28, -35.6726) to (18.8556, -43.2103)
  arc A7 centre (0.42, -0.0725) radius 1 clockwise from (-0.58, -0.0725) to (0.42, 0.9275)
  arc A8 centre (20.28, -0.0725) radius 1 clockwise from (20.28, 0.9275) to (21.28, -0.0725)
  point P3 (-0.58, -0.0725)
  point P20 (-0.58, -0.0725)
  point P2 (21.28, -0.0725)
  point P21 (21.28, -0.0725)
  point P12 (14.35, -56.3325)
  point P22 (14.35, -56.3325)
  point P10 (6.35, -56.3325)
  point P23 (6.35, -56.3325)
  point P24 (10.35, 0.9275)
  point P25 (10.35, -33.0725)
  coincident P3 P20
  coincident P2 P21
  coincident P12 P22
  coincident P10 P23
  midpoint L1 P24
  perpendicular L1 L9
  dimension "d411" distance P24 P25 = 34
sketch "Sketch29" plane through (10.35, 0, -28.2025) normal (0, -1, 0) x axis (1, 0, 0)
  line L1 (-10.93, -7.4701) -> (-10.93, 28.13)
  line L2 (-7.93, -24.2) -> (-7.93, -16.7975)
  line L3 (4, -28.13) -> (-4, -28.13)
  line L4 (7.93, -16.7975) -> (7.93, -24.2)
  line L5 (10.93, 28.13) -> (10.93, -7.4701)
  line L6 (-9.93, 29.13) -> (9.93, 29.13)
  line L7 (-4.072, 3.603) -> (4.072, 3.603)
  line L8 (4.072, 3.603) -> (4.072, -7.4701)
  line L9 (-4.072, -7.4701) -> (-4.072, 3.603)
  line L10 (-4.072, -2.9502) -> (4.072, -2.9502)
  arc A1 centre (-9.93, 28.13) radius 1 clockwise from (-10.93, 28.13) to (-9.93, 29.13)
  arc A2 centre (2, -7.4701) radius 12.93 clockwise from (-8.5056, -15.0078) to (-10.93, -7.4701)
  arc A3 centre (-11, -16.7975) radius 3.07 clockwise from (-8.5056, -15.0078) to (-7.93, -16.7975)
  arc A4 centre (-4, -24.2) radius 3.93 clockwise from (-4, -28.13) to (-7.93, -24.2)
  arc A5 centre (4, -24.2) radius 3.93 clockwise from (7.93, -24.2) to (4, -28.13)
  arc A6 centre (11, -16.7975) radius 3.07 clockwise from (7.93, -16.7975) to (8.5056, -15.0078)
  arc A7 centre (-2, -7.4701) radius 12.93 clockwise from (10.93, -7.4701) to (8.5056, -15.0078)
  arc A8 centre (9.93, 28.13) radius 1 clockwise from (9.93, 29.13) to (10.93, 28.13)
  dimension "d417" = -6.5532
fillet "Fillet44" radius 0.5
remove_body "RemoveBody1"
extrude "Extrude33" add sketch "Sketch29" profile of L7 L8 L9 L10 along normal blind 2
fillet "Fillet46" radius 1.5 0.5
fillet "Fillet34" radius 1
extrude "Extrude25" add sketch "extruded features z" profile of L11 L17 L18 L19 L20 to an object
extrude "Extrude24" add sketch "extruded features z" profile of L11 L17 L18 L19 L20 to an object
named bodies: "follower", "floor plate"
